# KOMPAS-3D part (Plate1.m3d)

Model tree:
1. Plane XY
2. Plane ZX
3. Plane ZY
4. X Axis
5. Y Axis
6. Z Axis
7. Origin
8. Sketch:1
9. Extrude:1
     Wall Thickness 1 = 1; Wall Thickness 2 = 1; Distance 1 = 10; Distance 2 = 20

Referenced files in D:\Documents and Settings\kashirsky\Рабочий стол\Seminar\: Cottage_balcony.a3d
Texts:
  Steel DIN 17102
  Three Point Plane
  Plane at Angle
  Line and Point Plane
  Axis through Two Vertices
  Axis of Feature
  Axis of Conical Surface
  Axis through Edge
  Trim by Surface
  Trim by Sketch
  Feature with No History
  Intersection Axis of Two Planes
  Two Line Plane
  Line and Face Plane
  Bend by line
  Hole in sheet body
  Cut in sheet body
  Point in CM
  Linear Dimension from Line to Point
  Surface Finish Symbol
  Geometric Tolerance Symbol
  Leader #1
  Leader #2
  Leader #3
  Shape Deviations and Datum
  Node point number
  Mark of coordination axis
  Node point designation
  Mark/Reference designation with leader
  Mark/reference designation on line
  Mark/Reference designation without leader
